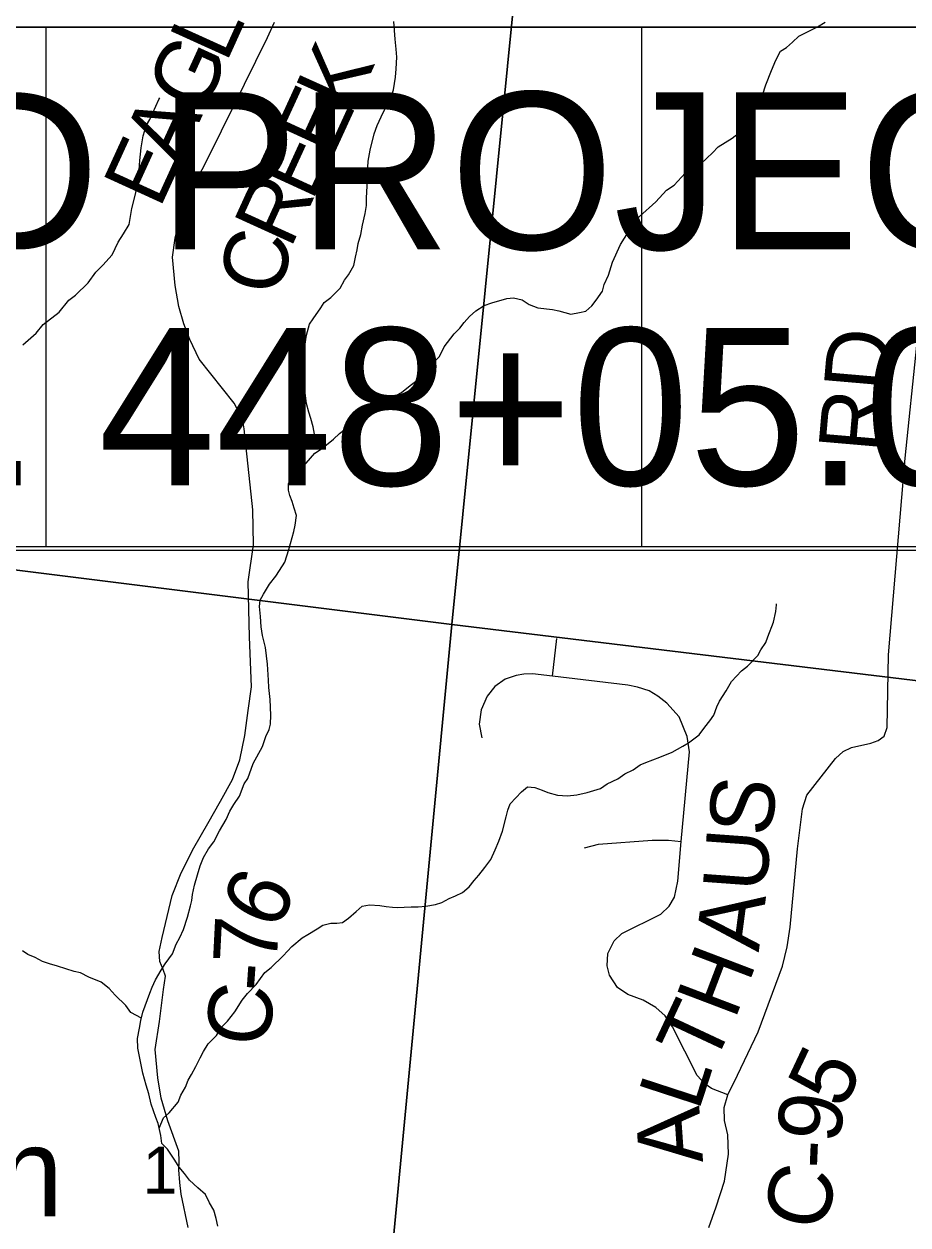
# Model space of a CAD drawing. Extents: x 0 to 34, y 0 to 22.
# Drawn here: x 5.092 to 5.879, y 17.665 to 18.734 of the extents above; entities that cross this region are included whole.
import ezdxf

# ---------------------------------------------------------------- set-up
doc = ezdxf.new("R2010")
doc.units = 0
for name, color, linetype in [('GM_X_County_Road', 7, 'Continuous'), ('GM_X_County_Road_Text', 7, 'Continuous'), ('GM_X_Minor_River', 7, 'Continuous'), ('GM_X_Section', 7, 'Continuous'), ('GM_X_Section_Text', 7, 'Continuous'), ('GM_X_Township_Road', 7, 'Continuous'), ('GM_X_Unincorporated_Text', 7, 'Continuous'), ('SH_Masking', 7, 'Continuous'), ('SH_Text', 7, 'Continuous')]:
    doc.layers.add(name, color=color, linetype=linetype)

msp = doc.modelspace()

# ---------------------------------------------------------------- linework, layer by layer
at = {"layer": 'GM_X_County_Road'}
for points in [[(5.2382, 17.6628), (5.2322, 17.6926), (5.231, 17.703), (5.2301, 17.7144), (5.2304, 17.7216), (5.2299, 17.7308), (5.2201, 17.7578), (5.2142, 17.7782), (5.2113, 17.7962), (5.209, 17.8213), (5.2127, 17.8463), (5.2165, 17.8747), (5.2183, 17.8868), (5.2162, 17.8926), (5.213, 17.8999), (5.2125, 17.9086), (5.2151, 17.9211), (5.2241, 17.9585), (5.2322, 17.9788), (5.2435, 18.0009), (5.2558, 18.0226), (5.267, 18.0424), (5.2778, 18.0619), (5.2843, 18.0792), (5.2887, 18.1011), (5.2916, 18.1231), (5.2948, 18.1443), (5.293, 18.1888), (5.2918, 18.2379), (5.2966, 18.2708), (5.296, 18.3018), (5.2881, 18.3739), (5.2868, 18.383), (5.2793, 18.3967), (5.2481, 18.436), (5.2399, 18.4534), (5.2345, 18.4676), (5.23, 18.4828), (5.2268, 18.5016), (5.2245, 18.5269), (5.2267, 18.5436), (5.2296, 18.5564), (5.2318, 18.5642), (5.2373, 18.5789), (5.2575, 18.6183), (5.3089, 18.7225), (5.3151, 18.7359)], [(5.7019, 17.6629), (5.7085, 17.6813), (5.7159, 17.7043), (5.7192, 17.7282), (5.7186, 17.7453), (5.7159, 17.7583), (5.7154, 17.7697), (5.7188, 17.781), (5.7272, 17.7986), (5.7457, 17.8372), (5.7675, 17.8956), (5.7717, 17.9129), (5.7741, 17.9303), (5.7809, 18), (5.7852, 18.0356), (5.789, 18.0477), (5.8146, 18.0805), (5.8215, 18.0867), (5.8288, 18.0903), (5.8461, 18.0941), (5.8527, 18.0964), (5.858, 18.1005), (5.8607, 18.1082), (5.8618, 18.1729), (5.8765, 18.348), (5.8869, 18.4482)]]:
    msp.add_lwpolyline(points, dxfattribs=at)
at = {"layer": 'GM_X_Minor_River'}
for points in [[(5.3582, 18.3572), (5.3509, 18.3693), (5.3496, 18.3758), (5.3475, 18.3831), (5.3458, 18.3888), (5.3438, 18.3965), (5.3426, 18.4057), (5.3414, 18.4145), (5.3405, 18.4225), (5.3413, 18.4323), (5.3416, 18.4407), (5.3422, 18.4475), (5.3437, 18.4573), (5.3463, 18.4671), (5.3495, 18.4719), (5.3563, 18.4816), (5.3595, 18.4864), (5.3653, 18.4908), (5.3736, 18.4992), (5.3776, 18.5063), (5.3812, 18.5111), (5.3857, 18.5193), (5.3874, 18.5269), (5.3888, 18.5333), (5.3898, 18.539), (5.3919, 18.5469), (5.3934, 18.5552), (5.396, 18.5657), (5.397, 18.5729), (5.3972, 18.5798), (5.3976, 18.59), (5.3976, 18.6006), (5.3982, 18.6067), (5.3987, 18.6124), (5.4002, 18.6222), (5.4038, 18.6365), (5.4067, 18.644), (5.41, 18.6519), (5.4165, 18.6646), (5.419, 18.6702), (5.4211, 18.6758), (5.423, 18.6872), (5.4236, 18.6944), (5.424, 18.705), (5.4234, 18.7119), (5.4226, 18.721), (5.4213, 18.7366)], [(5.378, 18.3737), (5.3842, 18.3792), (5.3993, 18.387), (5.406, 18.3929), (5.4126, 18.3976), (5.4192, 18.4015), (5.4281, 18.4062), (5.4359, 18.4127), (5.4444, 18.4189), (5.4504, 18.4259), (5.4555, 18.4318), (5.4622, 18.4384), (5.4663, 18.447), (5.4751, 18.4585), (5.4802, 18.4636), (5.4841, 18.4688), (5.4889, 18.474), (5.4944, 18.4791), (5.5017, 18.4838), (5.5087, 18.4862), (5.5221, 18.4899), (5.5278, 18.4905), (5.5357, 18.4887), (5.542, 18.4847), (5.5495, 18.4818), (5.5627, 18.4802), (5.5684, 18.4789), (5.5789, 18.4762), (5.5866, 18.4775), (5.5923, 18.4788), (5.5978, 18.4835), (5.6014, 18.4884), (5.6073, 18.4965), (5.6087, 18.5025), (5.6124, 18.5108), (5.6162, 18.5224), (5.6232, 18.5381), (5.6304, 18.5493), (5.6349, 18.5571), (5.64, 18.563), (5.6545, 18.5762), (5.664, 18.5865), (5.671, 18.5908), (5.6808, 18.6015), (5.6948, 18.6098), (5.6999, 18.6149), (5.705, 18.6197), (5.7101, 18.6252), (5.7225, 18.6328), (5.728, 18.6368), (5.7339, 18.6419), (5.7352, 18.6468), (5.7386, 18.6584), (5.7497, 18.671), (5.7527, 18.6804), (5.7576, 18.6931), (5.7614, 18.7021), (5.7655, 18.7103), (5.7709, 18.7136), (5.7764, 18.7183), (5.7819, 18.7235), (5.7927, 18.7288), (5.7985, 18.732), (5.8054, 18.7359)], [(5.1983, 18.6349), (5.2013, 18.6443), (5.2041, 18.6495), (5.2123, 18.6671), (5.213, 18.6687)], [(5.0913, 18.4489), (5.103, 18.4591), (5.1094, 18.4669), (5.1234, 18.4778), (5.1321, 18.4885), (5.138, 18.4929), (5.1494, 18.5039), (5.1562, 18.5136), (5.1624, 18.5198), (5.1707, 18.529), (5.1761, 18.5402), (5.1809, 18.5477), (5.1857, 18.5559), (5.1881, 18.5702), (5.1916, 18.5842), (5.1926, 18.5906), (5.1936, 18.5974), (5.1946, 18.6046), (5.1953, 18.6129), (5.1964, 18.6243), (5.1983, 18.6349)], [(5.2646, 17.6642), (5.2633, 17.6711), (5.2613, 17.6784), (5.2574, 17.685), (5.2538, 17.6924), (5.2468, 17.6983), (5.2394, 17.705), (5.2351, 17.7109), (5.2304, 17.7167), (5.2264, 17.7229), (5.2199, 17.7327), (5.2148, 17.7378), (5.2139, 17.7447), (5.2116, 17.7554), (5.2095, 17.7608), (5.2053, 17.7727), (5.2034, 17.7819), (5.201, 17.7896), (5.1979, 17.8003), (5.1954, 17.8137), (5.1934, 17.8225), (5.1933, 17.8313), (5.1951, 17.8403), (5.1961, 17.8471), (5.1979, 17.8547), (5.2042, 17.8715), (5.2063, 17.8768), (5.2092, 17.8835), (5.2144, 17.8921), (5.218, 17.8977), (5.2244, 17.9066), (5.2277, 17.9152), (5.231, 17.9212), (5.2343, 17.9283), (5.2377, 17.9392), (5.2403, 17.9493), (5.2416, 17.9542), (5.2422, 17.9595), (5.244, 17.9678), (5.2466, 17.9769), (5.2491, 17.9848), (5.252, 17.9923), (5.2565, 18.0001), (5.2613, 18.0064), (5.2661, 18.0161), (5.2722, 18.0262), (5.2755, 18.0336), (5.2791, 18.0396), (5.2839, 18.047), (5.2881, 18.0579), (5.2913, 18.0627), (5.2963, 18.0759), (5.3044, 18.0912), (5.3074, 18.1002), (5.3103, 18.1062), (5.3116, 18.1111), (5.3118, 18.119), (5.3112, 18.1331), (5.31, 18.1438), (5.3099, 18.1503), (5.3089, 18.1644), (5.3071, 18.1793), (5.3044, 18.19), (5.3032, 18.1976), (5.3027, 18.2068), (5.3019, 18.2159), (5.3025, 18.2216), (5.3053, 18.2268), (5.3106, 18.2358), (5.3165, 18.2428), (5.3197, 18.248), (5.3245, 18.2554), (5.328, 18.2667), (5.3323, 18.2825), (5.3336, 18.2882), (5.3347, 18.2969), (5.3326, 18.3034), (5.3309, 18.3092), (5.3288, 18.3146), (5.3275, 18.3195), (5.3277, 18.3249), (5.3337, 18.3334), (5.3435, 18.3433), (5.351, 18.3522), (5.3569, 18.3562), (5.3678, 18.3649), (5.3729, 18.3697), (5.378, 18.3737)], [(5.2124, 17.7515), (5.2163, 17.7605), (5.2214, 17.7649), (5.2293, 17.7745), (5.2318, 17.7809), (5.2359, 17.788), (5.2383, 17.794), (5.2412, 17.7992), (5.2452, 17.8063), (5.2489, 17.8141), (5.2521, 17.8197), (5.2562, 17.8264), (5.2636, 17.8338), (5.2677, 17.8409), (5.2732, 17.8467), (5.2799, 17.8549), (5.2864, 17.8653), (5.2911, 17.8712), (5.299, 17.8793), (5.3066, 17.8901), (5.3121, 17.8944), (5.323, 17.9047), (5.3305, 17.9132), (5.3399, 17.9208), (5.345, 17.9237), (5.3531, 17.9287), (5.3581, 17.932), (5.3654, 17.934), (5.3707, 17.9338), (5.3757, 17.9344), (5.3811, 17.9384), (5.3878, 17.9443), (5.3933, 17.949), (5.3998, 17.9503), (5.4089, 17.9496), (5.4145, 17.9487), (5.4202, 17.9481), (5.4251, 17.9479), (5.4305, 17.9481), (5.4369, 17.9483), (5.443, 17.9484), (5.4499, 17.949), (5.4586, 17.9506), (5.464, 17.9523), (5.4706, 17.9559), (5.4764, 17.9583), (5.4825, 17.9611), (5.4884, 17.9663), (5.4928, 17.9718), (5.4971, 17.9766), (5.5023, 17.9833), (5.5079, 17.9907), (5.5116, 17.9993), (5.5149, 18.0068), (5.5182, 18.0158), (5.5213, 18.0286), (5.523, 18.0346), (5.5251, 18.0402), (5.535, 18.0509), (5.5405, 18.0553), (5.5469, 18.0547), (5.5536, 18.0522), (5.5585, 18.0501), (5.5672, 18.0479), (5.5759, 18.0472), (5.5843, 18.0481), (5.5934, 18.0501), (5.6053, 18.0538), (5.6112, 18.0578), (5.6208, 18.0624), (5.627, 18.0668), (5.6344, 18.0703), (5.6406, 18.075), (5.6456, 18.0768), (5.6583, 18.0816), (5.6691, 18.0862), (5.6788, 18.0916), (5.6838, 18.0944), (5.6932, 18.1017), (5.6983, 18.1084), (5.7027, 18.1139), (5.7063, 18.1191), (5.7088, 18.1266), (5.7113, 18.1315), (5.7173, 18.1408), (5.7221, 18.149), (5.7308, 18.1586), (5.7363, 18.1626), (5.7453, 18.1721), (5.7482, 18.1773), (5.7526, 18.1837), (5.7543, 18.1889), (5.7593, 18.202), (5.7615, 18.2115), (5.7621, 18.2172), (5.7621, 18.2181)], [(5.1967, 17.8493), (5.1873, 17.8543), (5.1829, 17.8605), (5.1734, 17.8699), (5.1679, 17.8758), (5.1609, 17.8814), (5.15, 17.8859), (5.1426, 17.8896), (5.1369, 17.891), (5.1219, 17.8957), (5.1148, 17.8978), (5.1087, 17.8999), (5.102, 17.9032), (5.0957, 17.9061), (5.0908, 17.9093)]]:
    msp.add_lwpolyline(points, dxfattribs=at)
at = {"layer": 'GM_X_Section'}
for points in [[(5.5723, 19.1942), (5.4731, 18.1998), (4.5425, 18.316), (4.5239, 18.3316), (4.5093, 18.3513), (4.5006, 18.3701), (4.4914, 18.3942), (4.4948, 18.4581), (4.5809, 19.2879)], [(6.5612, 19.0743), (6.4651, 18.0799), (5.4731, 18.1998), (5.5723, 19.1942)], [(5.4731, 18.1998), (6.4651, 18.0799), (6.3631, 17.0951), (5.3785, 17.205)]]:
    msp.add_lwpolyline(points, close=True, dxfattribs=at)
msp.add_lwpolyline([(4.5425, 18.316), (5.4731, 18.1998), (5.3785, 17.205), (4.4409, 17.3119)], dxfattribs=at)
at = {"layer": 'GM_X_Township_Road'}
msp.add_line((5.5626, 18.1537), (5.5665, 18.1872), dxfattribs=at)
for points in [[(5.7188, 17.781), (5.7041, 17.7867), (5.6984, 17.7907), (5.6914, 17.7982), (5.6695, 17.8415), (5.6631, 17.8513), (5.6545, 17.8588), (5.6435, 17.8652), (5.6297, 17.8704), (5.6204, 17.8767), (5.6135, 17.8877), (5.6112, 17.8958), (5.6118, 17.9068), (5.6175, 17.9183), (5.6245, 17.9247), (5.6591, 17.942), (5.6666, 17.9489), (5.6712, 17.957), (5.6741, 17.9714), (5.6773, 18.0066), (5.6845, 18.0863), (5.6826, 18.1), (5.6753, 18.1175), (5.6645, 18.1297), (5.6564, 18.1361), (5.6487, 18.1406), (5.6383, 18.1441), (5.6297, 18.1458), (5.5626, 18.1537), (5.5449, 18.1558), (5.5372, 18.1557), (5.5304, 18.1545), (5.5205, 18.151), (5.5113, 18.1446), (5.5044, 18.136), (5.4992, 18.1239), (5.4974, 18.1112), (5.4998, 18.099)], [(5.591, 18.0009), (5.6037, 18.0043), (5.6513, 18.0077), (5.666, 18.0078), (5.6773, 18.0066)]]:
    msp.add_lwpolyline(points, dxfattribs=at)
at = {"layer": 'SH_Masking'}
for points in [[(4.5495, 18.2693), (5.6422, 18.2693), (5.6422, 18.7316), (4.5495, 18.7316)], [(5.1116, 18.2693), (6.2043, 18.2693), (6.2043, 18.7316), (5.1116, 18.7316)]]:
    msp.add_lwpolyline(points, close=True, dxfattribs=at)
at = {"layer": 'SH_Text'}
msp.add_lwpolyline([(4.5495, 18.7316), (6.2012, 18.7316), (6.2012, 18.2658), (4.5495, 18.2658)], close=True, dxfattribs=at)

# ---------------------------------------------------------------- texts
at = {"layer": 'GM_X_County_Road_Text'}
for s, height, rotation, p in [('L', 0.0568, 65.6014, (5.2721, 18.6989)), ('G', 0.0568, 65.4591, (5.2513, 18.6532)), ('K', 0.0568, 65.7806, (5.3843, 18.6534)), ('E', 0.0568, 65.3333, (5.3663, 18.6143)), ('A', 0.0568, 65.4564, (5.2305, 18.6078)), ('E', 0.0568, 65.3279, (5.3486, 18.5757)), ('E', 0.0568, 65.4555, (5.2129, 18.5691)), ('R', 0.0568, 65.5099, (5.3293, 18.5333)), ('C', 0.0568, 78.0155, (5.3206, 18.4907)), ('RD', 0.05682, 85.0728, (5.8559, 18.3516)), ('S', 0.0568, 82.5119, (5.7566, 18.0097)), ('U', 0.0568, 85.829, (5.753, 17.9607)), ('6', 0.0568, 65.034, (5.3175, 17.9257)), ('A', 0.0568, 82.5075, (5.7462, 17.9076)), ('7', 0.0568, 87.1242, (5.3171, 17.8963)), ('H', 0.0568, 69.1857, (5.7249, 17.8469)), ('-', 0.0568, 86.0145, (5.3154, 17.8719)), ('C', 0.0568, 83.011, (5.3094, 17.8223)), ('T', 0.0568, 64.9386, (5.7051, 17.8041)), ('5', 0.0568, 64.8117, (5.8214, 17.7668)), ('L', 0.0568, 71.9442, (5.6926, 17.7654)), ('A', 0.0568, 93.9538, (5.6967, 17.7213)), ('9', 0.0568, 81.5109, (5.8175, 17.7364)), ('-', 0.0568, 87.5463, (5.8167, 17.7146)), ('C', 0.0568, 76.5459, (5.8042, 17.6575))]:
    msp.add_text(s, height=height, rotation=rotation, dxfattribs=at).set_placement(p)
at = {"layer": 'GM_X_Section_Text'}
msp.add_text('1', height=0.0419, rotation=0, dxfattribs=at).set_placement((5.1977, 17.6931))
at = {"layer": 'GM_X_Unincorporated_Text'}
msp.add_text('Station', height=0.07898, rotation=0, dxfattribs=at).set_placement((4.7981, 17.673))
at = {"layer": 'SH_Text'}
for s, p in [('END PROJECT', (4.7642, 18.5337)), ('STA. 448+05.00 ', (4.6903, 18.3237))]:
    msp.add_text(s, height=0.14, dxfattribs=at).set_placement(p)

doc.saveas('drawing.dxf')
